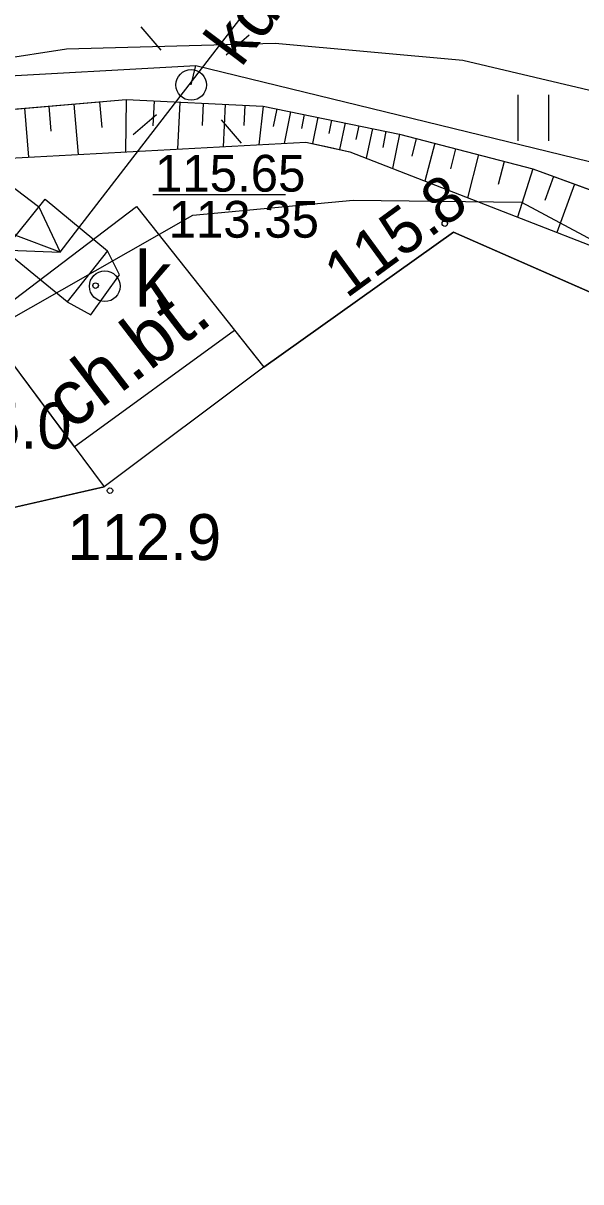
# Model space of a CAD drawing. Extents: x 6434771 to 6436222, y 5663454 to 5664782.
# Drawn here: x 6434931.92 to 6434941.02, y 5664024.77 to 5664043.67 of the extents above; entities that cross this region are included whole.
import ezdxf

# ---------------------------------------------------------------- set-up
doc = ezdxf.new("R2010")
doc.units = 0
for name, color, linetype in [('Warstwa 1', 7, 'Continuous'), ('Warstwa 10', 7, 'Continuous'), ('Warstwa 11', 7, 'Continuous'), ('Warstwa 12', 7, 'Continuous'), ('Warstwa 13', 7, 'Continuous'), ('Warstwa 14', 7, 'Continuous'), ('Warstwa 15', 7, 'Continuous'), ('Warstwa 2', 7, 'Continuous'), ('Warstwa 20', 7, 'Continuous'), ('Warstwa 21', 7, 'Continuous'), ('Warstwa 22', 7, 'Continuous'), ('Warstwa 4', 7, 'Continuous'), ('Warstwa 5', 7, 'Continuous'), ('Warstwa 6', 7, 'Continuous'), ('Warstwa 7', 7, 'Continuous'), ('Warstwa 9', 7, 'Continuous')]:
    doc.layers.add(name, color=color, linetype=linetype)

msp = doc.modelspace()

# ---------------------------------------------------------------- linework, layer by layer
at = {"layer": 'Warstwa 1'}
for p, q in [((6434934.693, 5664040.536), (6434937.307, 5664040.781)), ((6434937.307, 5664040.781), (6434940.056, 5664040.747)), ((6434940.056, 5664040.747), (6434955.627, 5664032.428)), ((6434931.371, 5664038.648), (6434934.693, 5664040.536))]:
    msp.add_line(p, q, dxfattribs=at)
at = {"layer": 'Warstwa 10'}
for p, q in [((6434930.459, 5664042.152), (6434933.603, 5664042.424)), ((6434932.341, 5664042.315), (6434932.377, 5664041.908)), ((6434932.75, 5664042.35), (6434932.821, 5664041.526)), ((6434933.17, 5664042.386), (6434933.206, 5664041.967)), ((6434933.603, 5664042.424), (6434933.593, 5664041.568)), ((6434933.603, 5664042.424), (6434935.842, 5664042.316)), ((6434934.06, 5664042.402), (6434934.041, 5664041.996)), ((6434934.479, 5664042.382), (6434934.443, 5664041.614)), ((6434934.864, 5664042.363), (6434934.847, 5664041.999)), ((6434935.218, 5664042.346), (6434935.185, 5664041.654)), ((6434935.543, 5664042.331), (6434935.527, 5664042.001)), ((6434935.842, 5664042.316), (6434935.771, 5664041.686)), ((6434935.842, 5664042.316), (6434938.067, 5664041.859)), ((6434931.945, 5664042.28), (6434932.014, 5664041.482)), ((6434936.065, 5664042.271), (6434936.006, 5664041.983)), ((6434936.288, 5664042.225), (6434936.182, 5664041.708)), ((6434936.51, 5664042.179), (6434936.463, 5664041.95)), ((6434936.733, 5664042.134), (6434936.645, 5664041.704)), ((6434936.954, 5664042.088), (6434936.91, 5664041.871)), ((6434937.177, 5664042.042), (6434937.087, 5664041.606)), ((6434937.399, 5664041.996), (6434937.353, 5664041.772)), ((6434937.622, 5664041.951), (6434937.522, 5664041.465)), ((6434937.844, 5664041.905), (6434937.79, 5664041.643)), ((6434938.067, 5664041.859), (6434937.948, 5664041.299)), ((6434938.067, 5664041.859), (6434940.24, 5664041.293)), ((6434938.339, 5664041.788), (6434938.263, 5664041.497)), ((6434929.479, 5664041.344), (6434936.535, 5664041.728)), ((6434936.535, 5664041.728), (6434936.894, 5664041.649)), ((6434936.894, 5664041.649), (6434937.253, 5664041.569)), ((6434937.253, 5664041.569), (6434943.086, 5664039.298)), ((6434938.642, 5664041.709), (6434938.48, 5664041.091)), ((6434938.979, 5664041.621), (6434938.894, 5664041.292)), ((6434939.355, 5664041.524), (6434939.172, 5664040.822)), ((6434939.773, 5664041.415), (6434939.676, 5664041.04)), ((6434940.24, 5664041.293), (6434939.992, 5664040.503)), ((6434940.24, 5664041.293), (6434942.361, 5664040.517)), ((6434940.577, 5664041.17), (6434940.435, 5664040.778)), ((6434940.921, 5664041.044), (6434940.632, 5664040.254))]:
    msp.add_line(p, q, dxfattribs=at)
at = {"layer": 'Warstwa 11'}
msp.add_lwpolyline([(6434966.756, 5664003.6), (6434966.415, 5664007.644), (6434965.276, 5664011.028), (6434962.407, 5664016.883), (6434961.412, 5664023.136), (6434959.23, 5664027.952), (6434956.702, 5664030.613), (6434952.189, 5664033.718), (6434942.648, 5664038.634), (6434938.947, 5664040.259), (6434935.85, 5664038.056), (6434933.246, 5664036.108), (6434929.415, 5664035.234), (6434925.755, 5664033.559), (6434924.242, 5664028.377), (6434923.988, 5664023.91), (6434923.741, 5664023.373), (6434924.496, 5664011.353), (6434925.122, 5664008.575), (6434925.857, 5664004.846)], dxfattribs=at)
at = {"layer": 'Warstwa 12'}
for points in [[(6434916.87, 5664040.657), (6434919.588, 5664040.514), (6434924.045, 5664039.35), (6434927.322, 5664041.55), (6434931.207, 5664042.783), (6434934.74, 5664042.98), (6434942.258, 5664041.148), (6434950.666, 5664036.716), (6434956.042, 5664033.861), (6434958.491, 5664032.141), (6434963.807, 5664027.637), (6434974.145, 5664019.101)], [(6434934.666, 5664042.661), (6434934.74, 5664042.98)]]:
    msp.add_lwpolyline(points, dxfattribs=at)
at = {"layer": 'Warstwa 13'}
for centre in [(6434938.803, 5664040.4), (6434933.341, 5664036.045)]:
    msp.add_circle(centre, 0.045, dxfattribs=at)
at = {"layer": 'Warstwa 14'}
msp.add_line((6434936.206, 5664040.869), (6434934.038, 5664040.869), dxfattribs=at)
msp.add_circle((6434933.106, 5664039.389), 0.045, dxfattribs=at)
at = {"layer": 'Warstwa 15'}
for points in [[(6434932.283, 5664040.8), (6434933.303, 5664039.957), (6434932.643, 5664039.125), (6434931.613, 5664039.968)], [(6434933.303, 5664039.957), (6434932.643, 5664039.125), (6434933.03, 5664038.91), (6434933.498, 5664039.565)]]:
    msp.add_lwpolyline(points, close=True, dxfattribs=at)
at = {"layer": 'Warstwa 2'}
msp.add_lwpolyline([(6434921.661, 5664034.898), (6434922.705, 5664038.576), (6434924.532, 5664039.094), (6434926.338, 5664040.422), (6434928.301, 5664041.518), (6434930.459, 5664042.152), (6434933.603, 5664042.424), (6434935.842, 5664042.316), (6434938.067, 5664041.859), (6434940.24, 5664041.293), (6434942.361, 5664040.517), (6434946.478, 5664038.627), (6434952.38, 5664035.426), (6434958.066, 5664031.766), (6434964.917, 5664026.013)], dxfattribs=at)
msp.add_circle((6434934.666, 5664042.661), 0.25, dxfattribs=at)
at = {"layer": 'Warstwa 20'}
for p, q in [((6434930.459, 5664042.152), (6434933.603, 5664042.424)), ((6434933.603, 5664042.424), (6434935.842, 5664042.316)), ((6434935.842, 5664042.316), (6434938.067, 5664041.859)), ((6434938.067, 5664041.859), (6434940.24, 5664041.293)), ((6434940.24, 5664041.293), (6434942.361, 5664040.517))]:
    msp.add_line(p, q, dxfattribs=at)
at = {"layer": 'Warstwa 21'}
for p, q in [((6434929.479, 5664041.344), (6434936.535, 5664041.728)), ((6434936.535, 5664041.728), (6434936.894, 5664041.649)), ((6434936.894, 5664041.649), (6434937.253, 5664041.569)), ((6434937.253, 5664041.569), (6434943.086, 5664039.298))]:
    msp.add_line(p, q, dxfattribs=at)
at = {"layer": 'Warstwa 22'}
for p, q in [((6434931.258, 5664038.772), (6434933.772, 5664040.681)), ((6434933.772, 5664040.681), (6434935.85, 5664038.056)), ((6434935.85, 5664038.056), (6434938.947, 5664040.259)), ((6434931.258, 5664038.772), (6434933.246, 5664036.108)), ((6434929.415, 5664035.234), (6434933.246, 5664036.108))]:
    msp.add_line(p, q, dxfattribs=at)
at = {"layer": 'Warstwa 4'}
for points in [[(6434934.176, 5664043.229), (6434933.85, 5664043.608)], [(6434935.234, 5664043.151), (6434935.613, 5664043.477)], [(6434934.098, 5664042.171), (6434933.719, 5664041.845)], [(6434935.156, 5664042.093), (6434935.482, 5664041.714)]]:
    msp.add_lwpolyline(points, dxfattribs=at)
msp.add_circle((6434933.256, 5664039.378), 0.25, dxfattribs=at)
at = {"layer": 'Warstwa 5'}
for p, q in [((6434932.633, 5664043.248), (6434936.037, 5664043.343)), ((6434936.037, 5664043.343), (6434939.097, 5664043.063)), ((6434929.643, 5664042.796), (6434932.633, 5664043.248)), ((6434939.097, 5664043.063), (6434941.871, 5664042.413)), ((6434930.459, 5664042.152), (6434933.603, 5664042.424)), ((6434933.603, 5664042.424), (6434935.842, 5664042.316)), ((6434935.842, 5664042.316), (6434938.067, 5664041.859)), ((6434940.003, 5664041.749), (6434940.003, 5664042.499)), ((6434940.503, 5664041.749), (6434940.503, 5664042.499)), ((6434938.067, 5664041.859), (6434940.24, 5664041.293)), ((6434929.479, 5664041.344), (6434936.535, 5664041.728)), ((6434936.535, 5664041.728), (6434937.253, 5664041.569)), ((6434937.253, 5664041.569), (6434943.086, 5664039.298)), ((6434940.24, 5664041.293), (6434942.361, 5664040.517)), ((6434931.258, 5664038.772), (6434933.772, 5664040.681)), ((6434933.772, 5664040.681), (6434935.372, 5664038.66)), ((6434935.85, 5664038.056), (6434938.947, 5664040.259)), ((6434938.947, 5664040.259), (6434941.184, 5664039.277)), ((6434935.372, 5664038.66), (6434935.85, 5664038.056))]:
    msp.add_line(p, q, dxfattribs=at)
at = {"layer": 'Warstwa 6'}
msp.add_circle((6434933.106, 5664039.389), 0.045, dxfattribs=at)
at = {"layer": 'Warstwa 7'}
msp.add_lwpolyline([(6434931.805, 5664040.206), (6434931.787, 5664040.222), (6434928.208, 5664042.939), (6434927.618, 5664043.361), (6434881.848, 5664073.028), (6434882.174, 5664073.532), (6434927.956, 5664043.857), (6434928.564, 5664043.423), (6434932.177, 5664040.68), (6434932.182, 5664040.675), (6434932.526, 5664039.935)], close=True, dxfattribs=at)
for points in [[(6434932.526, 5664039.935), (6434932.833, 5664040.333), (6434937.258, 5664046.07), (6434937.622, 5664046.315), (6434938.316, 5664046.028), (6434960.883, 5664034.772), (6434973.659, 5664021.147), (6434974.001, 5664020.658), (6434974.526, 5664016.746), (6434981.103, 5663994.095), (6434983.279, 5663980.96)], [(6434914.535, 5664031.225), (6434914.846, 5664032.684), (6434918.879, 5664041.67), (6434931.703, 5664039.967), (6434932.526, 5664039.935)]]:
    msp.add_lwpolyline(points, dxfattribs=at)
at = {"layer": 'Warstwa 9'}
for p, q in [((6434932.633, 5664043.248), (6434936.037, 5664043.343)), ((6434936.037, 5664043.343), (6434939.097, 5664043.063)), ((6434929.643, 5664042.796), (6434932.633, 5664043.248)), ((6434939.097, 5664043.063), (6434941.871, 5664042.413)), ((6434931.258, 5664038.772), (6434933.772, 5664040.681)), ((6434933.772, 5664040.681), (6434935.372, 5664038.66)), ((6434931.258, 5664038.772), (6434932.759, 5664036.761)), ((6434932.759, 5664036.761), (6434935.372, 5664038.66))]:
    msp.add_line(p, q, dxfattribs=at)

# ---------------------------------------------------------------- texts
at = {"layer": 'Warstwa 13'}
msp.add_text('115.8', height=0.75, rotation=36.1135, dxfattribs=at).set_placement((6434937.198, 5664039.169))
for s, p in [('115.0', (6434930.205, 5664036.73)), ('112.9', (6434932.646, 5664034.913))]:
    msp.add_text(s, height=0.75, dxfattribs=at).set_placement(p)
at = {"layer": 'Warstwa 14'}
msp.add_text('113.35', height=0.6, dxfattribs=at).set_placement((6434934.297, 5664040.17))
at = {"layer": 'Warstwa 5'}
msp.add_text('k', height=0.9, dxfattribs=at).set_placement((6434933.744, 5664039.046))
at = {"layer": 'Warstwa 6'}
msp.add_text('115.65', height=0.6, dxfattribs=at).set_placement((6434934.075, 5664040.921))
at = {"layer": 'Warstwa 7'}
msp.add_text('kd250', height=0.8, rotation=53.0502, dxfattribs=at).set_placement((6434935.479, 5664042.93))
at = {"layer": 'Warstwa 9'}
msp.add_text('ch.bt.', height=0.9, rotation=37.5058, dxfattribs=at).set_placement((6434932.712, 5664037.011))

doc.saveas('drawing.dxf')
